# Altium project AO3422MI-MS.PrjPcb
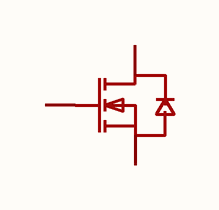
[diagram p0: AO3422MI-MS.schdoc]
1 sheet, 1 parts. Net scope: global (net labels, ports and power ports of the same name join across sheets).

## Sheet AO3422MI-MS.schdoc
size 127 x 101 mm

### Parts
Q?  ao3422mi-ms  [SOT-23-3_L3.0-W1.6-P1.90-LS2.8-BR]  (value not drawn)

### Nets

Not connected (* = marked no-connect by the designer): Q? 1(G) 2(S) 3(D)

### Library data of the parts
Q? = ao3422mi-ms: 数量:1个N沟道;漏源电压(Vdss):60V;连续漏极电流(Id):4.5A;导通电阻(RDS(on)):70mΩ@10V;耗散功率(Pd):8W;阈值电压(Vgs(th)):2.5V;; Manufacturer: MSKSEMI(美森科); AddInBom: yes; ModelId: 9c001725612240e7be81cfaae32ec359; ModelTransform: 114.173,116.535,0,0,0,0,0,0,0; Number: 1个N沟道; Drain to Source Voltage: 60V; Current - Continuous Drain(Id): 4.5A; Pd - Power Dissipation: 8W; Gate Threshold Voltage (Vgs(th)): 2.5V; Gate Charge(Qg): 5.5nC@10V; Input Capacitance(Ciss): 695pF; Reverse Transfer Capacitance (Crss@Vds): 7pF; Type: N沟道; Output Capacitance(Coss): 148pF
